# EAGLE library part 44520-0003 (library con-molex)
STACKED MODULAR JACK CATEGORY 5 Source: http://www.molex.com/pdm_docs/sd/445200006_sd.pdf
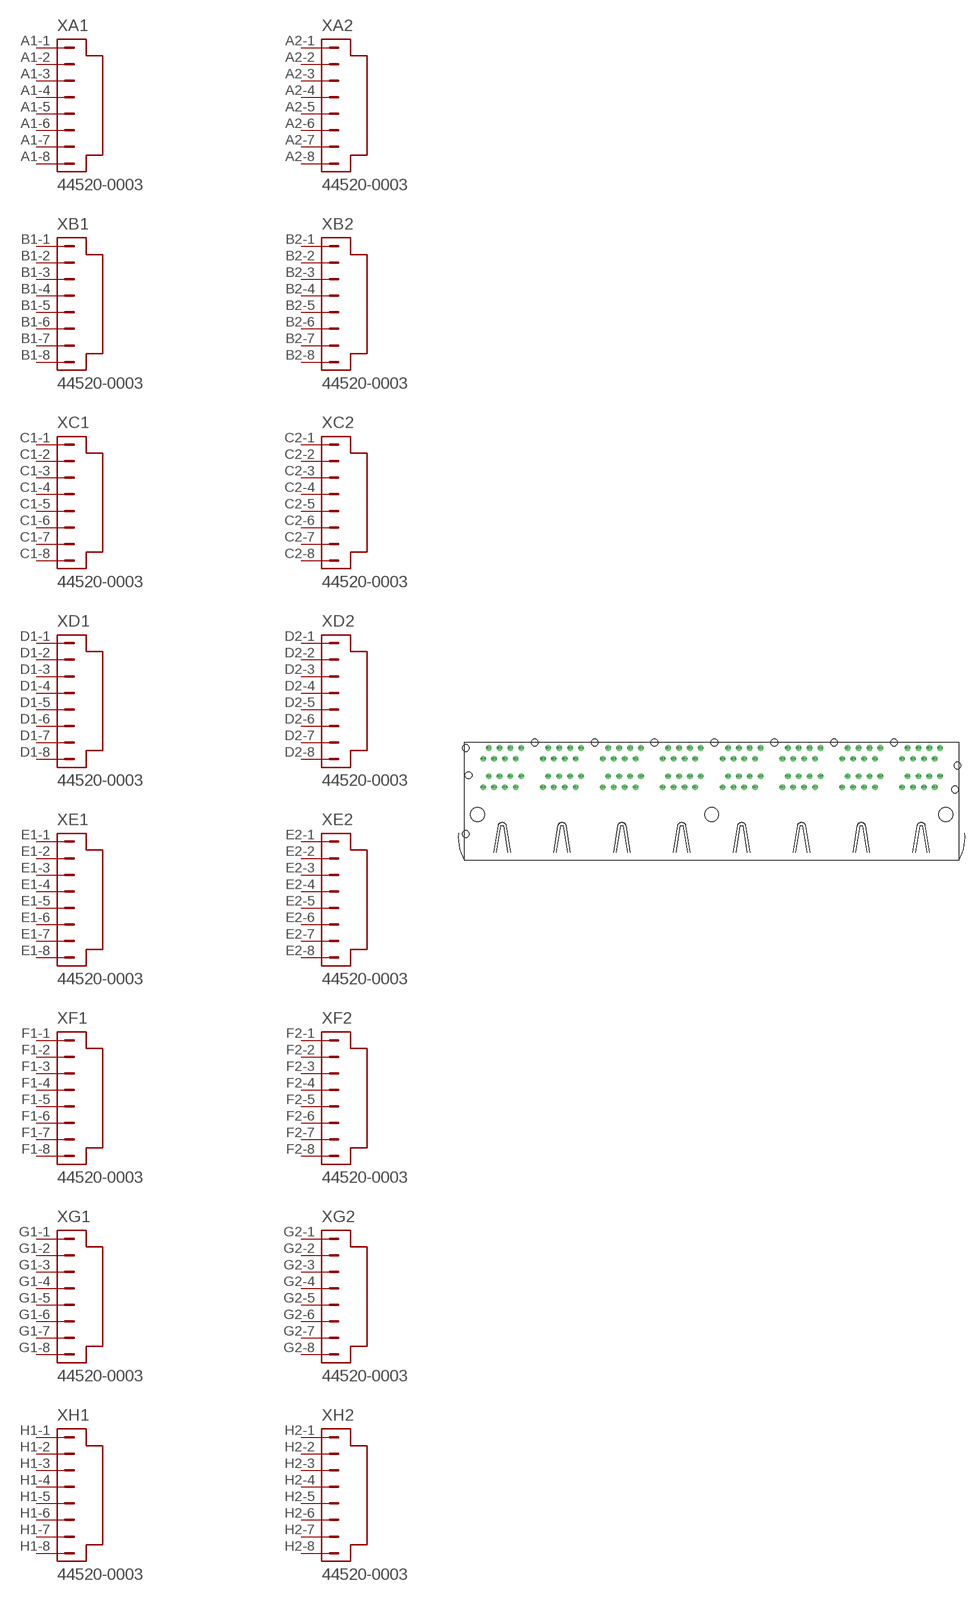
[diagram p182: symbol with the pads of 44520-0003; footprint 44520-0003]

Designator prefix X; gates A1=CON-1X8 A2=CON-1X8 B1=CON-1X8 B2=CON-1X8 C1=CON-1X8 C2=CON-1X8 D1=CON-1X8 D2=CON-1X8 E1=CON-1X8 E2=CON-1X8 F1=CON-1X8 F2=CON-1X8 G1=CON-1X8 G2=CON-1X8 H1=CON-1X8 H2=CON-1X8

## 44520-0003 (MPN: 44520-0003; OC_FARNELL: unknown; OC_NEWARK: 92M2841)  [44520-0003]
A1-1  A1:1  pas
A1-2  A1:2  pas
A1-3  A1:3  pas
A1-4  A1:4  pas
A1-5  A1:5  pas
A1-6  A1:6  pas
A1-7  A1:7  pas
A1-8  A1:8  pas
A2-1  A2:1  pas
A2-2  A2:2  pas
A2-3  A2:3  pas
A2-4  A2:4  pas
A2-5  A2:5  pas
A2-6  A2:6  pas
A2-7  A2:7  pas
A2-8  A2:8  pas
B1-1  B1:1  pas
B1-2  B1:2  pas
B1-3  B1:3  pas
B1-4  B1:4  pas
B1-5  B1:5  pas
B1-6  B1:6  pas
B1-7  B1:7  pas
B1-8  B1:8  pas
B2-1  B2:1  pas
B2-2  B2:2  pas
B2-3  B2:3  pas
B2-4  B2:4  pas
B2-5  B2:5  pas
B2-6  B2:6  pas
B2-7  B2:7  pas
B2-8  B2:8  pas
C1-1  C1:1  pas
C1-2  C1:2  pas
C1-3  C1:3  pas
C1-4  C1:4  pas
C1-5  C1:5  pas
C1-6  C1:6  pas
C1-7  C1:7  pas
C1-8  C1:8  pas
C2-1  C2:1  pas
C2-2  C2:2  pas
C2-3  C2:3  pas
C2-4  C2:4  pas
C2-5  C2:5  pas
C2-6  C2:6  pas
C2-7  C2:7  pas
C2-8  C2:8  pas
D1-1  D1:1  pas
D1-2  D1:2  pas
D1-3  D1:3  pas
D1-4  D1:4  pas
D1-5  D1:5  pas
D1-6  D1:6  pas
D1-7  D1:7  pas
D1-8  D1:8  pas
D2-1  D2:1  pas
D2-2  D2:2  pas
D2-3  D2:3  pas
D2-4  D2:4  pas
D2-5  D2:5  pas
D2-6  D2:6  pas
D2-7  D2:7  pas
D2-8  D2:8  pas
E1-1  E1:1  pas
E1-2  E1:2  pas
E1-3  E1:3  pas
E1-4  E1:4  pas
E1-5  E1:5  pas
E1-6  E1:6  pas
E1-7  E1:7  pas
E1-8  E1:8  pas
E2-1  E2:1  pas
E2-2  E2:2  pas
E2-3  E2:3  pas
E2-4  E2:4  pas
E2-5  E2:5  pas
E2-6  E2:6  pas
E2-7  E2:7  pas
E2-8  E2:8  pas
F1-1  F1:1  pas
F1-2  F1:2  pas
F1-3  F1:3  pas
F1-4  F1:4  pas
F1-5  F1:5  pas
F1-6  F1:6  pas
F1-7  F1:7  pas
F1-8  F1:8  pas
F2-1  F2:1  pas
F2-2  F2:2  pas
F2-3  F2:3  pas
F2-4  F2:4  pas
F2-5  F2:5  pas
F2-6  F2:6  pas
F2-7  F2:7  pas
F2-8  F2:8  pas
G1-1  G1:1  pas
G1-2  G1:2  pas
G1-3  G1:3  pas
G1-4  G1:4  pas
G1-5  G1:5  pas
G1-6  G1:6  pas
G1-7  G1:7  pas
G1-8  G1:8  pas
G2-1  G2:1  pas
G2-2  G2:2  pas
G2-3  G2:3  pas
G2-4  G2:4  pas
G2-5  G2:5  pas
G2-6  G2:6  pas
G2-7  G2:7  pas
G2-8  G2:8  pas
H1-1  H1:1  pas
H1-2  H1:2  pas
H1-3  H1:3  pas
H1-4  H1:4  pas
H1-5  H1:5  pas
H1-6  H1:6  pas
H1-7  H1:7  pas
H1-8  H1:8  pas
H2-1  H2:1  pas
H2-2  H2:2  pas
H2-3  H2:3  pas
H2-4  H2:4  pas
H2-5  H2:5  pas
H2-6  H2:6  pas
H2-7  H2:7  pas
H2-8  H2:8  pas

## Footprint 44520-0003 (pad centres in mm)
STACKED MODULAR JACK CATEGORY 5 Source: http://www.molex.com/pdm_docs/sd/445200006_sd.pdf
drill 0.8 round: A1-1 -53.34,6.35; A1-2 -52.07,8.89; A1-3 -50.8,6.35; A1-4 -49.53,8.89; A1-5 -48.26,6.35; A1-6 -46.99,8.89; A1-7 -45.72,6.35; A1-8 -44.45,8.89; A2-1 -44.45,15.494; A2-2 -45.72,12.954; A2-3 -46.99,15.494; A2-4 -48.26,12.954; A2-5 -49.53,15.494; A2-6 -50.8,12.954; A2-7 -52.07,15.494; A2-8 -53.34,12.954; B1-1 -39.37,6.35; B1-2 -38.1,8.89; B1-3 -36.83,6.35; B1-4 -35.56,8.89; B1-5 -34.29,6.35; B1-6 -33.02,8.89; B1-7 -31.75,6.35; B1-8 -30.48,8.89; B2-1 -30.48,15.494; B2-2 -31.75,12.954; B2-3 -33.02,15.494; B2-4 -34.29,12.954; B2-5 -35.56,15.494; B2-6 -36.83,12.954; B2-7 -38.1,15.494; B2-8 -39.37,12.954; C1-1 -25.4,6.35; C1-2 -24.13,8.89; C1-3 -22.86,6.35; C1-4 -21.59,8.89; C1-5 -20.32,6.35; C1-6 -19.05,8.89; C1-7 -17.78,6.35; C1-8 -16.51,8.89; C2-1 -16.51,15.494; C2-2 -17.78,12.954; C2-3 -19.05,15.494; C2-4 -20.32,12.954; C2-5 -21.59,15.494; C2-6 -22.86,12.954; C2-7 -24.13,15.494; C2-8 -25.4,12.954; D1-1 -11.43,6.35; D1-2 -10.16,8.89; D1-3 -8.89,6.35; D1-4 -7.62,8.89; D1-5 -6.35,6.35; D1-6 -5.08,8.89; D1-7 -3.81,6.35; D1-8 -2.54,8.89; D2-1 -2.54,15.494; D2-2 -3.81,12.954; D2-3 -5.08,15.494; D2-4 -6.35,12.954; D2-5 -7.62,15.494; D2-6 -8.89,12.954; D2-7 -10.16,15.494; D2-8 -11.43,12.954; E1-1 2.54,6.35; E1-2 3.81,8.89; E1-3 5.08,6.35; E1-4 6.35,8.89; E1-5 7.62,6.35; E1-6 8.89,8.89; E1-7 10.16,6.35; E1-8 11.43,8.89; E2-1 11.43,15.494; E2-2 10.16,12.954; E2-3 8.89,15.494; E2-4 7.62,12.954; E2-5 6.35,15.494; E2-6 5.08,12.954; E2-7 3.81,15.494; E2-8 2.54,12.954; F1-1 16.51,6.35; F1-2 17.78,8.89; F1-3 19.05,6.35; F1-4 20.32,8.89; F1-5 21.59,6.35; F1-6 22.86,8.89; F1-7 24.13,6.35; F1-8 25.4,8.89; F2-1 24.13,12.954; F2-2 25.4,15.494; F2-3 22.86,15.494; F2-4 21.59,12.954; F2-5 20.32,15.494; F2-6 19.05,12.954; F2-7 17.78,15.494; F2-8 16.51,12.954; G1-1 30.48,6.35; G1-2 31.75,8.89; G1-3 33.02,6.35; G1-4 34.29,8.89; G1-5 35.56,6.35; G1-6 36.83,8.89; G1-7 38.1,6.35; G1-8 39.37,8.89; G2-1 39.37,15.494; G2-2 38.1,12.954; G2-3 36.83,15.494; G2-4 35.56,12.954; G2-5 34.29,15.494; G2-6 33.02,12.954; G2-7 31.75,15.494; G2-8 30.48,12.954; H1-1 44.45,6.35; H1-2 45.72,8.89; H1-3 46.99,6.35; H1-4 48.26,8.89; H1-5 49.53,6.35; H1-6 50.8,8.89; H1-7 52.07,6.35; H1-8 53.34,8.89; H2-1 53.34,15.494; H2-2 52.07,12.954; H2-3 50.8,15.494; H2-4 49.53,12.954; H2-5 48.26,15.494; H2-6 46.99,12.954; H2-7 45.72,15.494; H2-8 44.45,12.954
hole 1.575 at -57.404,-4.572
hole 3.251 at 54.61,0
hole 1.575 at -56.769,9.144
hole 1.575 at -57.404,15.494
hole 1.575 at -41.275,16.764
hole 1.575 at -27.305,16.764
hole 1.575 at -13.335,16.764
hole 1.575 at 0.635,16.764
hole 1.575 at 14.605,16.764
hole 1.575 at 28.575,16.764
hole 1.575 at 42.545,16.764
hole 3.251 at 0,0
hole 1.575 at 56.769,5.842
hole 1.575 at 57.404,11.43
hole 3.251 at -54.61,0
